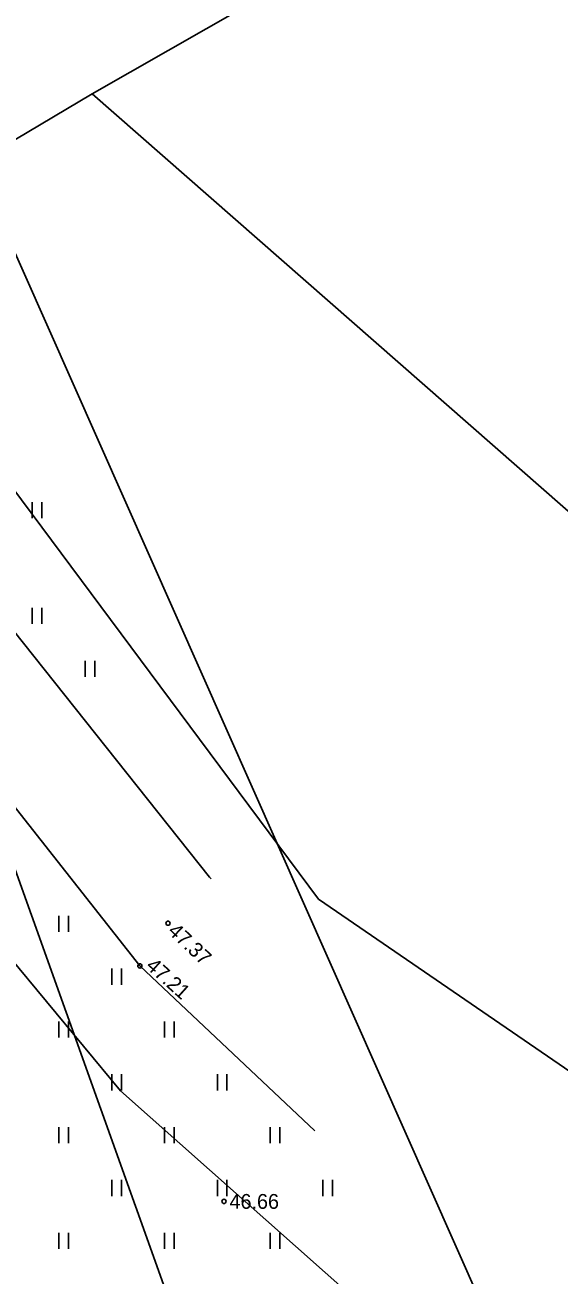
# Model space of a CAD drawing. Extents: x 642747 to 644424, y 6457048 to 6458238.
# Drawn here: x 644114.7 to 644140, y 6457646.8 to 6457705.9 of the extents above; entities that cross this region are included whole.
import ezdxf

# ---------------------------------------------------------------- set-up
doc = ezdxf.new("R2010")
doc.units = 0
for name, color, linetype in [('HALJASTUS', 7, 'Continuous'), ('KORGUS', 7, 'Continuous'), ('MOOTPIIR', 7, 'Continuous'), ('PIIR', 7, 'Continuous'), ('TEE', 7, 'Continuous'), ('VORMISTUS', 7, 'Continuous')]:
    doc.layers.add(name, color=color, linetype=linetype)

msp = doc.modelspace()

# ---------------------------------------------------------------- linework, layer by layer
at = {"layer": 'HALJASTUS'}
for p, q in [((644115.029, 6457683.356), (644115.029, 6457682.595)), ((644115.484, 6457683.356), (644115.484, 6457682.595)), ((644115.029, 6457678.356), (644115.029, 6457677.595)), ((644115.484, 6457678.356), (644115.484, 6457677.595)), ((644117.529, 6457675.856), (644117.529, 6457675.095)), ((644117.984, 6457675.856), (644117.984, 6457675.095)), ((644116.29, 6457663.789), (644116.29, 6457663.028)), ((644116.745, 6457663.789), (644116.745, 6457663.028)), ((644118.79, 6457661.289), (644118.79, 6457660.528)), ((644119.245, 6457661.289), (644119.245, 6457660.528)), ((644116.29, 6457658.789), (644116.29, 6457658.028)), ((644116.745, 6457658.789), (644116.745, 6457658.028)), ((644121.29, 6457658.789), (644121.29, 6457658.028)), ((644121.745, 6457658.789), (644121.745, 6457658.028)), ((644118.79, 6457656.289), (644118.79, 6457655.528)), ((644119.245, 6457656.289), (644119.245, 6457655.528)), ((644123.79, 6457656.289), (644123.79, 6457655.528)), ((644124.245, 6457656.289), (644124.245, 6457655.528)), ((644116.29, 6457653.789), (644116.29, 6457653.028)), ((644116.745, 6457653.789), (644116.745, 6457653.028)), ((644121.29, 6457653.789), (644121.29, 6457653.028)), ((644121.745, 6457653.789), (644121.745, 6457653.028)), ((644126.29, 6457653.789), (644126.29, 6457653.028)), ((644126.745, 6457653.789), (644126.745, 6457653.028)), ((644118.79, 6457651.289), (644118.79, 6457650.528)), ((644119.245, 6457651.289), (644119.245, 6457650.528)), ((644123.79, 6457651.289), (644123.79, 6457650.528)), ((644124.245, 6457651.289), (644124.245, 6457650.528)), ((644128.79, 6457651.289), (644128.79, 6457650.528)), ((644129.245, 6457651.289), (644129.245, 6457650.528)), ((644116.29, 6457648.789), (644116.29, 6457648.028)), ((644116.745, 6457648.789), (644116.745, 6457648.028)), ((644121.29, 6457648.789), (644121.29, 6457648.028)), ((644121.745, 6457648.789), (644121.745, 6457648.028)), ((644126.29, 6457648.789), (644126.29, 6457648.028)), ((644126.745, 6457648.789), (644126.745, 6457648.028))]:
    msp.add_line(p, q, dxfattribs=at)
at = {"layer": 'KORGUS'}
for centre in [(644121.453, 6457663.437), (644120.122, 6457661.417), (644124.104, 6457650.274)]:
    msp.add_circle(centre, 0.1, dxfattribs=at)
at = {"layer": 'MOOTPIIR'}
msp.add_lwpolyline([(643525.446, 6457467.559), (643537.447, 6457435.458), (643944.848, 6457628.51), (644046.626, 6457529.09), (644067.022, 6457529.09), (644138.408, 6457598.401), (644075.1, 6457775.215), (644046.02, 6457752.582), (644092.466, 6457611.94), (644070.657, 6457576.375), (644041.981, 6457570.717), (643942.223, 6457662.862)], close=True, dxfattribs=at)
at = {"layer": 'PIIR'}
for points in [[(644172.44, 6457634.51), (644128.57, 6457664.58), (644105.62, 6457695.4), (644084.27, 6457738.29), (644082.35, 6457742.69), (644071.37, 6457766.77), (644068.6, 6457772.82), (644052.27, 6457804.54)], [(644056.78, 6457779.28), (644062.47, 6457766.56), (644060.34, 6457762.97), (644041.41, 6457742.89), (644054.5, 6457738.54), (644058.72, 6457740.17), (644055.31, 6457749.58), (644061, 6457751.62), (644060.21, 6457753.82), (644065.16, 6457760.36), (644069.76, 6457744.43), (644073.59, 6457731.16), (644087.56, 6457695.23), (644092.09, 6457697.08), (644102.74, 6457676.12), (644108.68, 6457668.18), (644119.21, 6457655.5), (644137.18, 6457639.57)]]:
    msp.add_lwpolyline(points, dxfattribs=at)
for points in [[(644084.27, 6457738.29), (644105.62, 6457695.4), (644117.87, 6457702.68), (644141.47, 6457716.14), (644166.4, 6457723.98), (644161.44, 6457753.91), (644160.79, 6457756.77), (644152.83, 6457754.95), (644133.56, 6457751.83), (644087.35, 6457749.32), (644082.35, 6457742.69)], [(644141.47, 6457716.14), (644117.87, 6457702.68), (644155.89, 6457669.35), (644185.98, 6457698.94), (644166.4, 6457723.98)]]:
    msp.add_lwpolyline(points, close=True, dxfattribs=at)
at = {"layer": 'TEE'}
for points in [[(644061.722, 6457771.823), (644064.397, 6457766.262), (644069.452, 6457755.916), (644076.842, 6457739.337), (644084.183, 6457724.283), (644091.562, 6457708.571), (644100.441, 6457690.483), (644108.831, 6457675.729), (644120.122, 6457661.417), (644128.409, 6457653.611)], [(644123.504, 6457665.54), (644123.416, 6457665.621), (644113.131, 6457678.523), (644106.187, 6457690.082), (644107.056, 6457690.755), (644112.042, 6457693.41)]]:
    msp.add_lwpolyline(points, dxfattribs=at)
at = {"layer": 'VORMISTUS'}
msp.add_line((644034.968, 6457873.554), (644180.435, 6457546.05), dxfattribs=at)

# ---------------------------------------------------------------- texts
at = {"layer": 'KORGUS'}
for s, rotation, p in [(' 47.37', 316.46077, (644121.212, 6457663.184)), (' 47.21', 317.97376, (644120.17, 6457661.522))]:
    msp.add_text(s, height=0.7, rotation=rotation, dxfattribs=at).set_placement(p)
msp.add_text(' 46.66', height=0.7, dxfattribs=at).set_placement((644124.104, 6457649.924))

doc.saveas('drawing.dxf')
